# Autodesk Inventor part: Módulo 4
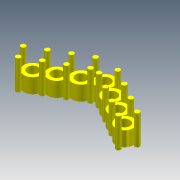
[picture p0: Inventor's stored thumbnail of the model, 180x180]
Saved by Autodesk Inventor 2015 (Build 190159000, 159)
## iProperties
Created: 2015-04
Part Number: Módulo 4
Material: Generic
Document SubType Name: Modeling
Designer: Gabriel Cabellos
Density: 1 g/cm^3
Appearance: Default
Author: Gabriel Cabellos
Sending System: SolidWorks 2008
Last Author: welington
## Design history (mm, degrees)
node "Módulo 41"
node "Modulo4"
node "Base1"
